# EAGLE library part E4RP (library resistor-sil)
SIL RESISTOR
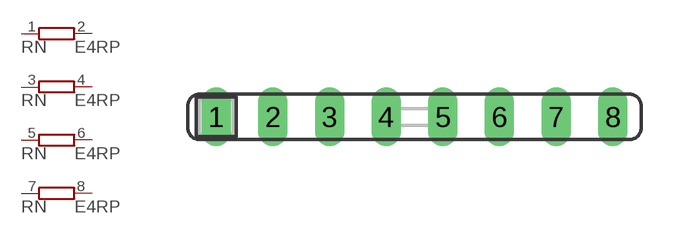
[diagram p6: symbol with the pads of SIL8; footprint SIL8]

Designator prefix RN; gates A=RPV B=RPV C=RPV D=RPV

## E4RP (OC_FARNELL: unknown; OC_NEWARK: unknown)  [SIL8]
1  A:1  pas
2  A:2  pas
3  B:1  pas
4  B:2  pas
5  C:1  pas
6  C:2  pas
7  D:1  pas
8  D:2  pas

## Footprint SIL8 (pad centres in mm)
Single In Line
drill 0.813 long: 1 -8.89,0; 2 -6.35,0; 3 -3.81,0; 4 -1.27,0; 5 1.27,0; 6 3.81,0; 7 6.35,0; 8 8.89,0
